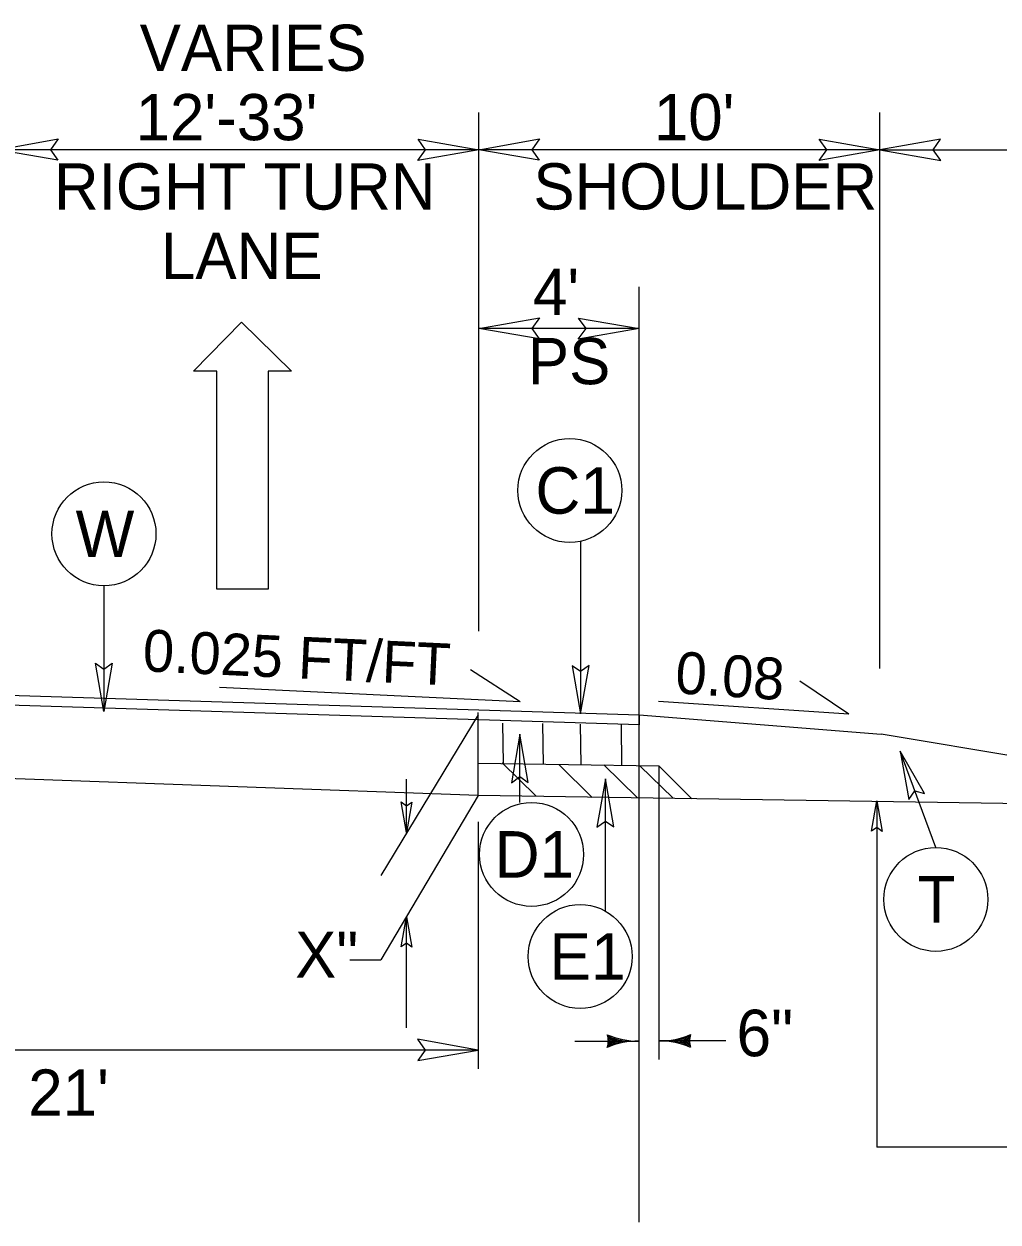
# Model space of a CAD drawing. Extents: x 2176156 to 2177167, y 76401 to 76644.
# Drawn here: x 2177009.62 to 2177033.9, y 76588.04 to 76617.92 of the extents above; entities that cross this region are included whole.
import ezdxf

# ---------------------------------------------------------------- set-up
doc = ezdxf.new("R2010")
doc.units = 0
for name, color, linetype in [('Exist Building', 7, 'Continuous'), ('Exist Roads Curbs', 7, 'Continuous'), ('Exist Roads EOP Other', 7, 'Continuous'), ('Exist Roads Soil', 7, 'Continuous'), ('Exist Structure Minor Culvert Topo', 7, 'Continuous'), ('Exist Structure Minor Drop Inlet', 7, 'Continuous'), ('Exist Utilities Other Pole CELL', 7, 'Continuous'), ('Model Boundary Lines Text', 7, 'Continuous'), ('Old_Level_1', 7, 'Continuous'), ('Old_Level_3', 7, 'Continuous'), ('Prop North Arrow NAD83 for Plan Sheets CELL', 7, 'Continuous'), ('Sheet Plan CELL', 7, 'Continuous')]:
    doc.layers.add(name, color=color, linetype=linetype)

msp = doc.modelspace()

# ---------------------------------------------------------------- linework, layer by layer
at = {"layer": 'Exist Building'}
for p, q in [((2177020.947, 76598.67), (2177020.947, 76600.743)), ((2177042.063, 76598.356), (2177020.947, 76598.67))]:
    msp.add_line(p, q, dxfattribs=at)
at = {"layer": 'Exist Roads Curbs'}
msp.add_lwpolyline([(2177008.961, 76601.183), (2177008.96, 76601.183), (2177024.96, 76600.684), (2177024.96, 76600.433), (2177008.96, 76600.933), (2177008.96, 76600.933)], close=True, dxfattribs=at)
at = {"layer": 'Exist Roads EOP Other'}
msp.add_line((2177024.96, 76600.684), (2177030.995, 76600.201), dxfattribs=at)
at = {"layer": 'Exist Roads Soil'}
for p, q in [((2177024.947, 76600.683), (2177024.948, 76599.417)), ((2177058.947, 76595.542), (2177030.995, 76600.201)), ((2177020.947, 76599.477), (2177025.452, 76599.41)), ((2177025.452, 76599.41), (2177026.275, 76598.591))]:
    msp.add_line(p, q, dxfattribs=at)
at = {"layer": 'Exist Structure Minor Drop Inlet'}
for p, q in [((2177013.845, 76609.254), (2177015.048, 76610.476)), ((2177015.048, 76610.476), (2177016.29, 76609.254)), ((2177014.427, 76609.254), (2177013.845, 76609.254)), ((2177014.427, 76603.822), (2177014.427, 76609.254)), ((2177016.29, 76609.254), (2177015.708, 76609.254)), ((2177015.708, 76609.254), (2177015.708, 76603.822)), ((2177015.708, 76603.822), (2177014.427, 76603.822))]:
    msp.add_line(p, q, dxfattribs=at)
at = {"layer": 'Exist Utilities Other Pole CELL'}
for p, q in [((2177021.996, 76601.014), (2177020.756, 76601.81)), ((2177030.187, 76600.704), (2177028.963, 76601.524)), ((2177021.996, 76601.014), (2177014.498, 76601.364)), ((2177030.187, 76600.704), (2177025.441, 76601.018))]:
    msp.add_line(p, q, dxfattribs=at)
at = {"layer": 'Model Boundary Lines Text'}
for p, q in [((2177021.573, 76599.47), (2177021.559, 76600.481)), ((2177022.571, 76599.446), (2177022.556, 76600.472)), ((2177023.511, 76599.439), (2177023.497, 76600.453)), ((2177024.529, 76599.425), (2177024.515, 76600.441)), ((2177022.383, 76598.667), (2177021.547, 76599.485)), ((2177023.791, 76598.626), (2177022.955, 76599.445)), ((2177024.91, 76598.622), (2177024.074, 76599.441)), ((2177025.803, 76598.604), (2177024.977, 76599.414))]:
    msp.add_line(p, q, dxfattribs=at)
at = {"layer": 'Old_Level_1'}
for points in [[(2177010.469, 76614.521), (2177008.96, 76614.781), (2177010.478, 76615.049), (2177010.285, 76614.781)], [(2177019.45, 76615.041), (2177020.96, 76614.781), (2177019.442, 76614.513), (2177019.635, 76614.781)], [(2177022.469, 76614.521), (2177020.96, 76614.781), (2177022.478, 76615.049), (2177022.285, 76614.781)], [(2177029.45, 76615.041), (2177030.96, 76614.781), (2177029.442, 76614.513), (2177029.635, 76614.781)], [(2177032.469, 76615.041), (2177030.96, 76614.781), (2177032.478, 76614.513), (2177032.285, 76614.781)], [(2177022.469, 76610.061), (2177020.96, 76610.321), (2177022.478, 76610.589), (2177022.285, 76610.321)], [(2177023.45, 76610.581), (2177024.96, 76610.321), (2177023.442, 76610.052), (2177023.635, 76610.321)], [(2177019.291, 76598.508), (2177019.159, 76597.753), (2177019.027, 76598.513), (2177019.161, 76598.416)], [(2177030.75, 76597.782), (2177030.88, 76598.537), (2177031.014, 76597.778), (2177030.88, 76597.875)], [(2177019.026, 76594.897), (2177019.158, 76595.652), (2177019.29, 76594.892), (2177019.157, 76594.989)], [(2177019.437, 76592.066), (2177020.947, 76592.326), (2177019.429, 76592.595), (2177019.622, 76592.326)]]:
    msp.add_lwpolyline(points, close=True, dxfattribs=at)
at = {"layer": 'Old_Level_3'}
for p, q in [((2177020.96, 76602.769), (2177020.96, 76615.709)), ((2177030.96, 76601.841), (2177030.96, 76615.709)), ((2177020.96, 76614.781), (2177008.96, 76614.781)), ((2177030.96, 76614.781), (2177020.96, 76614.781)), ((2177030.96, 76614.781), (2177042.96, 76614.781)), ((2177024.96, 76588.036), (2177024.96, 76611.357)), ((2177024.96, 76610.321), (2177020.96, 76610.321)), ((2177020.947, 76600.686), (2177018.522, 76596.678)), ((2177019.159, 76597.753), (2177019.159, 76599.081)), ((2177020.947, 76598.671), (2177018.522, 76594.576)), ((2177030.88, 76598.537), (2177030.88, 76589.902)), ((2177020.947, 76598.021), (2177020.947, 76591.858)), ((2177019.158, 76592.876), (2177019.158, 76595.652)), ((2177017.742, 76594.576), (2177018.522, 76594.576)), ((2176981.96, 76592.329), (2177020.96, 76592.329)), ((2177040.448, 76589.902), (2177030.88, 76589.902))]:
    msp.add_line(p, q, dxfattribs=at)
at = {"layer": 'Prop North Arrow NAD83 for Plan Sheets CELL'}
for p, q in [((2177023.495, 76605.015), (2177023.495, 76600.712)), ((2177011.616, 76603.904), (2177011.616, 76600.771)), ((2177021.985, 76598.501), (2177021.985, 76600.2)), ((2177032.355, 76597.379), (2177031.466, 76599.781)), ((2177024.952, 76599.417), (2177024.952, 76592.049)), ((2177025.452, 76599.405), (2177025.452, 76592.09)), ((2177024.116, 76595.793), (2177024.116, 76599.089)), ((2177023.352, 76592.549), (2177024.952, 76592.549)), ((2177027.119, 76592.552), (2177025.452, 76592.552))]:
    msp.add_line(p, q, dxfattribs=at)
for points in [[(2177011.823, 76601.971), (2177011.616, 76600.771), (2177011.403, 76601.977), (2177011.616, 76601.824)], [(2177023.288, 76601.912), (2177023.495, 76600.712), (2177023.708, 76601.918), (2177023.495, 76601.765)], [(2177022.192, 76599), (2177021.985, 76600.2), (2177021.772, 76598.993), (2177021.985, 76599.147)], [(2177032.076, 76598.728), (2177031.466, 76599.781), (2177031.684, 76598.576), (2177031.831, 76598.793)], [(2177024.323, 76597.889), (2177024.116, 76599.089), (2177023.903, 76597.882), (2177024.116, 76598.035)]]:
    msp.add_lwpolyline(points, close=True, dxfattribs=at)
for centre in [(2177023.229, 76606.283), (2177011.616, 76605.2), (2177022.276, 76597.205), (2177032.355, 76596.083), (2177023.487, 76594.66)]:
    msp.add_circle(centre, 1.296, dxfattribs=at)
for centre, radius, start, end in [((2177023.743, 76592.549), 0.448, 339.2339, 20.7656), ((2177024.927, 76594.464), 1.915, 246.4844, 270.7618), ((2177024.927, 76590.633), 1.915, 89.2377, 113.5151), ((2177024.927, 76594.464), 1.942, 247.1889, 260.4633), ((2177024.927, 76590.633), 1.942, 99.5361, 112.8105), ((2177024.927, 76594.464), 1.969, 247.7692, 256.611), ((2177024.927, 76590.633), 1.969, 103.3884, 112.2302), ((2177024.927, 76594.464), 1.995, 248.2497, 253.7027), ((2177024.927, 76590.633), 1.995, 106.2968, 111.7497), ((2177024.927, 76594.464), 2.022, 248.6468, 251.2909), ((2177024.927, 76590.633), 2.022, 108.7086, 111.3527), ((2177025.477, 76594.467), 1.915, 269.2378, 293.5152), ((2177025.477, 76590.637), 1.915, 66.4845, 90.7619), ((2177025.477, 76594.467), 1.942, 279.5362, 292.8107), ((2177025.477, 76590.637), 1.942, 67.189, 80.4635), ((2177025.477, 76594.467), 1.969, 283.3885, 292.2304), ((2177025.477, 76590.637), 1.969, 67.7693, 76.6112), ((2177025.477, 76594.467), 1.995, 286.2969, 291.7498), ((2177025.477, 76590.637), 1.995, 68.2499, 73.7028), ((2177025.477, 76594.467), 2.022, 288.7087, 291.3528), ((2177025.477, 76590.637), 2.022, 68.6469, 71.291), ((2177026.661, 76592.552), 0.448, 159.234, 200.7657)]:
    msp.add_arc(centre, radius, start, end, dxfattribs=at)
at = {"layer": 'Sheet Plan CELL'}
msp.add_line((2177020.947, 76598.67), (2176993.96, 76599.648), dxfattribs=at)

# ---------------------------------------------------------------- texts
at = {"layer": 'Exist Structure Minor Culvert Topo'}
for s, height, p in [('VARIES ', 1.1533, (2177012.506, 76616.747)), ("12'-33' ", 1.1533, (2177012.404, 76615.017)), ("10' ", 1.1533, (2177025.324, 76615.019)), ('RIGHT TURN ', 1.15334, (2177010.371, 76613.287)), ('SHOULDER', 1.1533, (2177022.322, 76613.289)), ('LANE', 1.1533, (2177013.037, 76611.557)), ("4' ", 1.1533, (2177022.312, 76610.662)), ('PS', 1.1533, (2177022.183, 76608.932)), ("EXIST. PAVEMENT 21'", 1.15334, (2176995.503, 76590.688))]:
    msp.add_text(s, height=height, dxfattribs=at).set_placement(p)
at = {"layer": 'Exist Utilities Other Pole CELL'}
for s, height, rotation, p in [('0.025 FT/FT', 1.04295, 357.3324, (2177012.567, 76601.776)), ('0.08', 1.0429, 356.2199, (2177025.837, 76601.228))]:
    msp.add_text(s, height=height, rotation=rotation, dxfattribs=at).set_placement(p)
at = {"layer": 'Prop North Arrow NAD83 for Plan Sheets CELL'}
for s, rotation, p in [('C1', 359.9997, (2177022.373, 76605.703)), ('W', 0.0003, (2177010.909, 76604.62)), ('D1', 359.9997, (2177021.355, 76596.625)), ('T', 359.9997, (2177031.898, 76595.503)), ('E1', 359.9997, (2177022.724, 76594.08)), ('6"', 359.9998, (2177027.385, 76592.171))]:
    msp.add_text(s, height=1.16, rotation=rotation, dxfattribs=at).set_placement(p)
msp.add_text('X"', height=1.1533, dxfattribs=at).set_placement((2177016.38, 76594.127))

doc.saveas('drawing.dxf')
